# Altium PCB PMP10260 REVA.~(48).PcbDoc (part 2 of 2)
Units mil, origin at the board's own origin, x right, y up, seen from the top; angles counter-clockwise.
Board outline 5118.11 x 4724.41 mil, 4 copper layers (Top Layer, MidLayer1, MidLayer2, Bottom Layer), stack 63.8 mil thick; 175 components, 80 nets, 424 pads, 447 vias.
Unrouted connection lines stored in the file: 1.
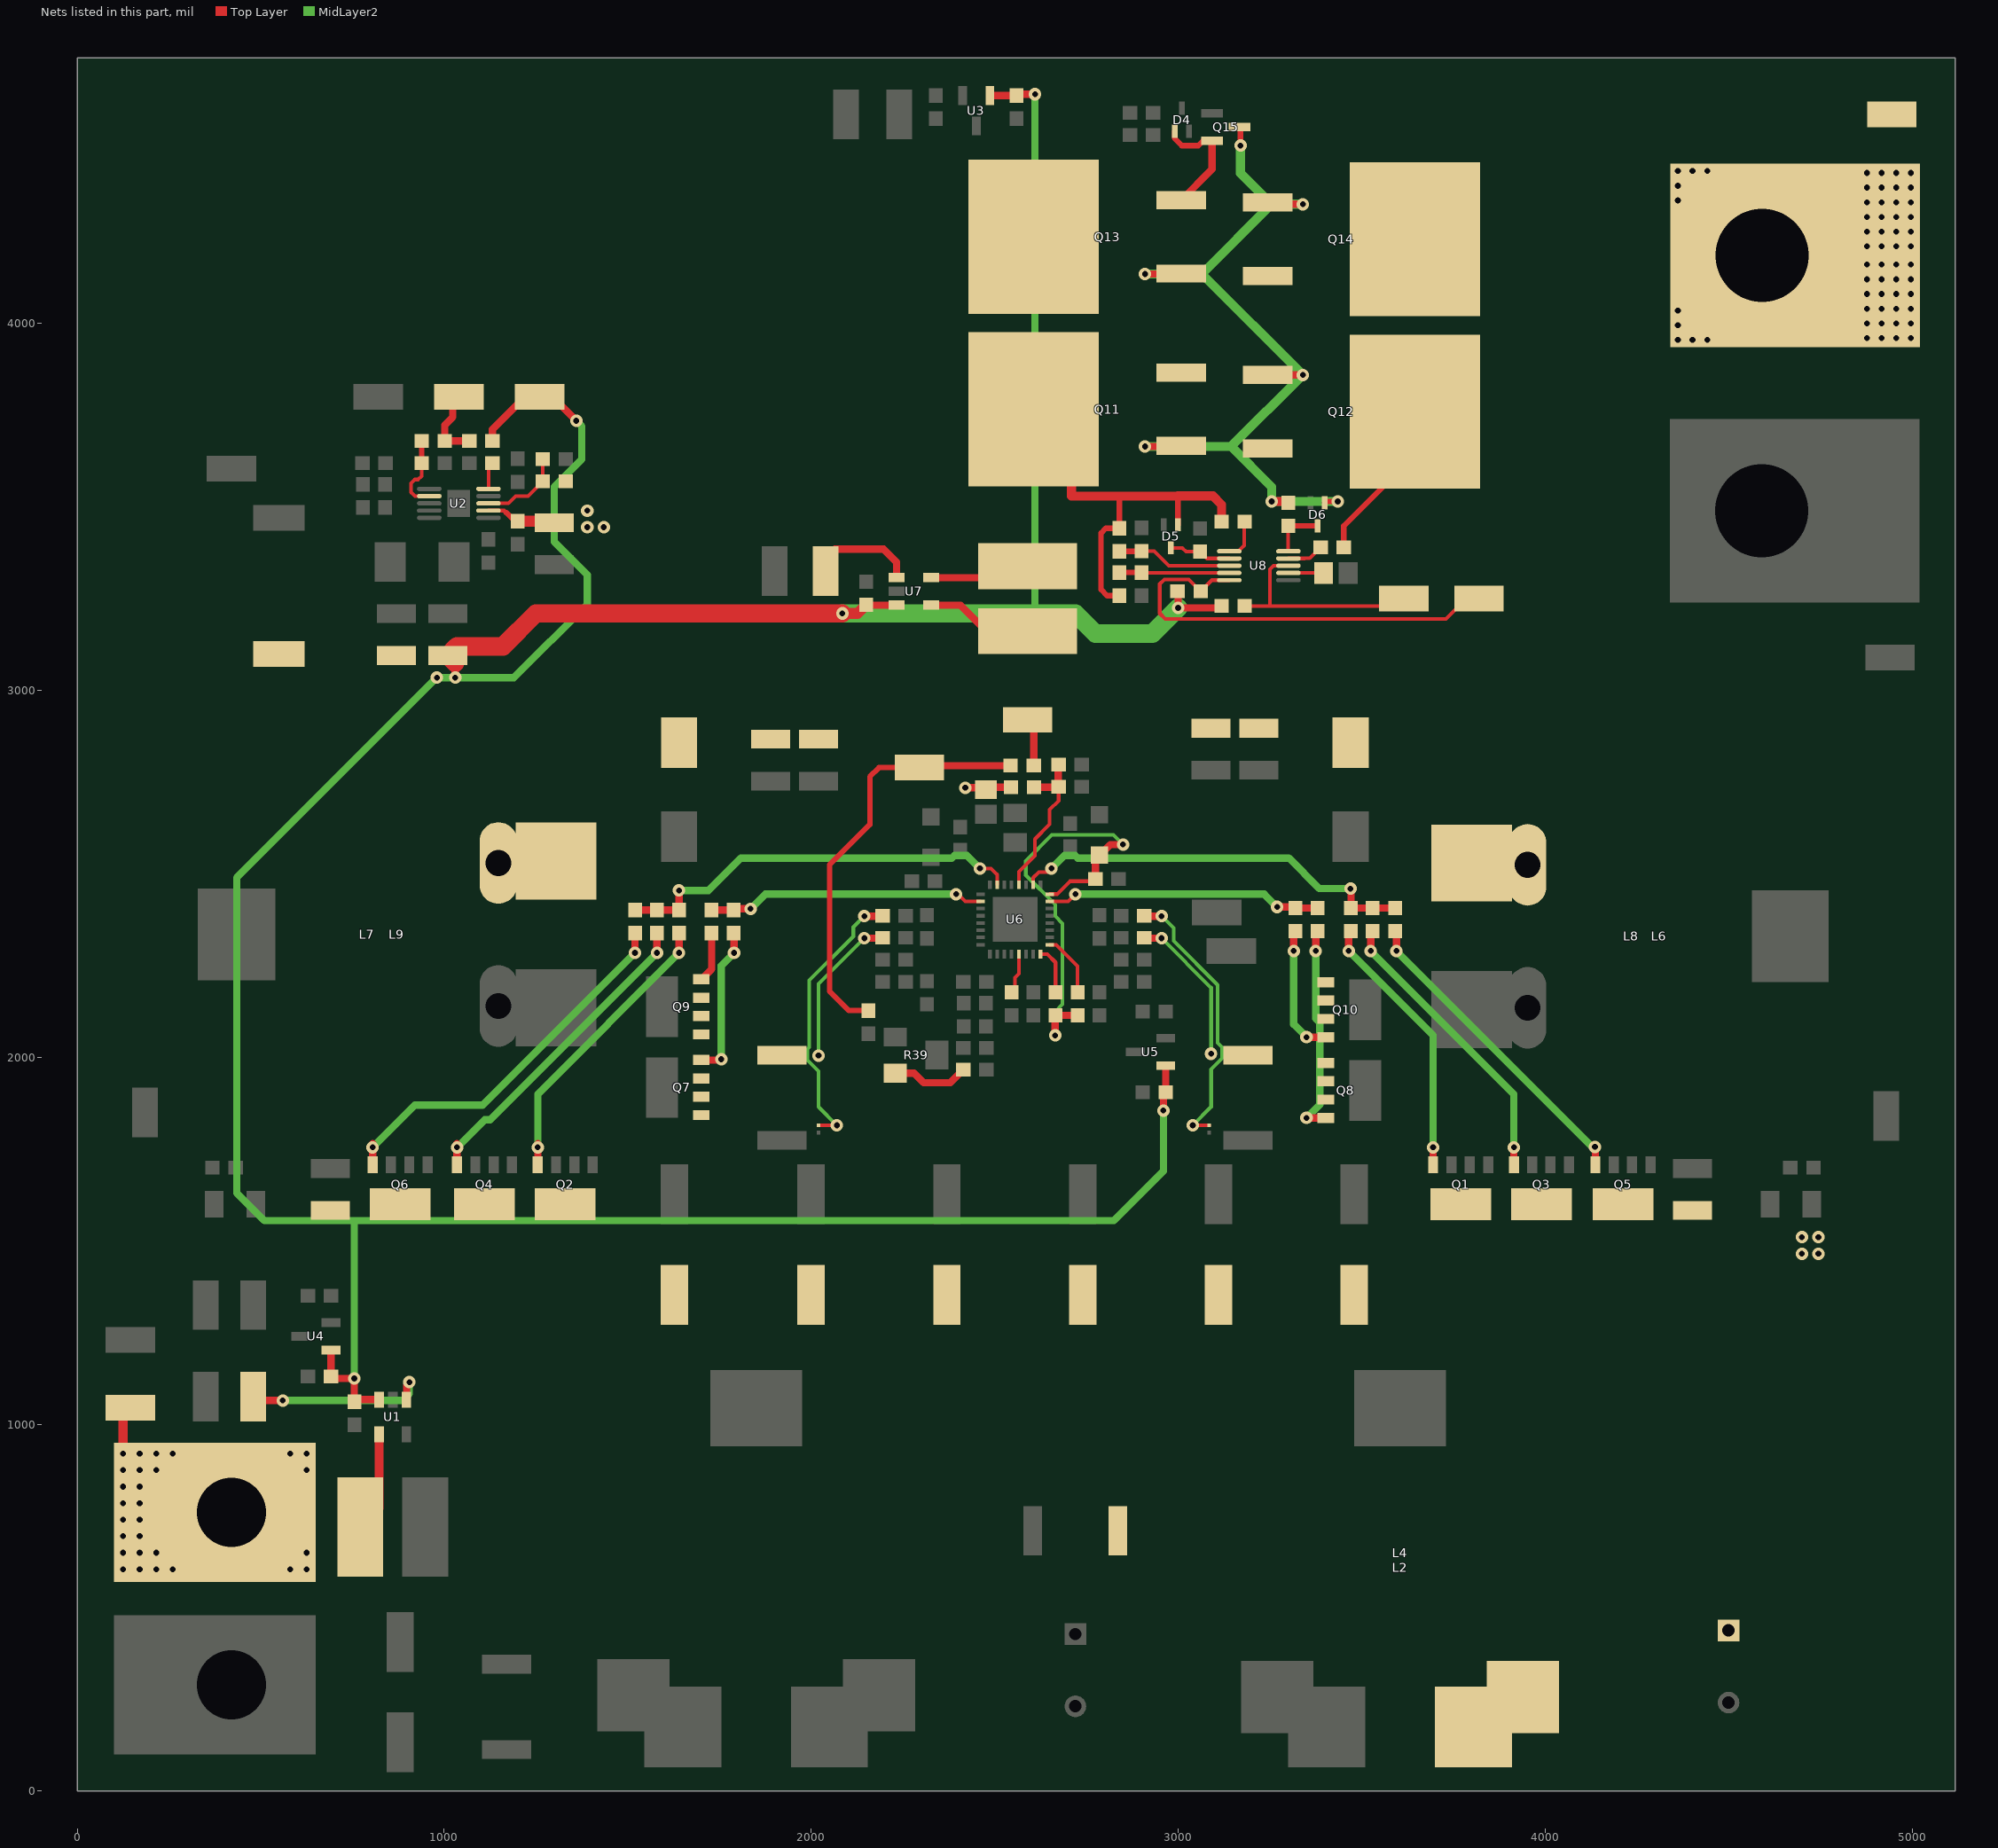
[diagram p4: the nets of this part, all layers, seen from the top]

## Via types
v1: diameter 34, hole 16, Top Layer to Bottom Layer, 260 vias
v2: diameter 32, hole 16, Top Layer to Bottom Layer, 172 vias
v3: diameter 19.68, hole 7.87, Top Layer to Bottom Layer, 10 vias
v4: diameter 200, hole 150, Top Layer to Bottom Layer, 5 vias

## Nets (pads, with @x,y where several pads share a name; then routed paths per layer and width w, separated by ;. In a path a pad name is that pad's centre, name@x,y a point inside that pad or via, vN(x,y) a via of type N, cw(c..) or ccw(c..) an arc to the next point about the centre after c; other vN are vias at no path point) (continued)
NetC52_1: C52.1 D5.3 U8.2 | length 171.2
  Top Layer w10: D5.3@2980,3388.5 3011.5,3388.5 3021.5,3378.5 C52.1@3060,3378.5 3078.82,3359.69 U8.2@3139.29,3359.69
NetC53_1: C53.1 U8.7 | length 96
  Top Layer w10: U8.7@3300.71,3320.31 3396.22,3320.31 C53.1@3396.54,3320
NetD4_1: D4.1 Q11.3 Q12.3 Q13.3 Q14.3 Q15.2 | length 332
  Top Layer w15: D4.1@2990.51,4523.9 2990.51,4504.49 3010,4485 3055,4485 3067.99,4497.99 Q15.2@3092.8,4497.99
  Top Layer w20: Q13.3@3008.15,4336.18 3092.8,4420.83 Q15.2@3092.8,4497.99
NetD5_1: D5.1 Q11.4 Q13.4 R43.2 R45.2 R46.2 R47.2 U7.5 | length 1509.8
  Top Layer w15: Q11.4@2606.57,3766.18 2606.57,3708.43 Q11.4@2709.69,3605.31 ; R46.2@2840,3258.5 2806.5,3258.5 2790,3275 2790,3428.94 2803.03,3441.97 R47.2@2840,3441.97 2840,3529.69 ; D5.1@2999.69,3451.5 2999.69,3529.69
  Top Layer w20: U7.5@2327.24,3307.4 2558.82,3307.4 R43.2@2590,3338.58
  Top Layer w25: Q11.4@2709.69,3663.07 2709.69,3605.31 2709.69,3529.69 2840,3529.69 2999.69,3529.69 ; 2999.69,3530 3095,3530 3118.5,3506.5 R45.2@3118.5,3460
NetD6_1: D6.1 Q11.1 Q12.1 Q13.1 Q14.1 Q15.3 R48.1 | length 2505.2
  Top Layer w15: Q15.3@3167.6,4535.39 3170,4532.99 v1(3170,4485) ; D6.1@3399.68,3511.5 3403.19,3515 v1(3435,3515)
  Top Layer w20: v1(2910,3665) 3006.97,3665 Q11.1@3008.15,3666.18 ; v1(2910,4135) 3006.97,4135 Q13.1@3008.15,4136.18 ; Q12.1@3243.94,3860 v1(3340,3860) ; Q14.1@3243.94,4330 3248.94,4325 v1(3340,4325)
  Top Layer w25: v1(3255,3515) 3296.5,3515 R48.1@3300,3511.5
  MidLayer2 w25: v1(2910,3665) 3145,3665 ; v1(2910,4135) 3065,4135 ; v1(3170,4485) 3170,4410 3255,4325 ; v1(3340,4325) 3255,4325 ; v1(3435,3515) v1(3255,3515) 3255,3555 3145,3665 ; 3065,4135 v1(3340,3860) 3145,3665 ; 3065,4135 3255,4325
NetD6_3: D6.3 R48.2 U8.10 | length 149.4
  Top Layer w10: R48.2@3300,3448.5 3300,3380.08 U8.10@3300.71,3379.37
  Top Layer w15: R48.2@3300,3448.5 D6.3@3380,3448.5
NetNT1_1: NT1.1 R34.2 | length 764.4
  Top Layer w10: v1(3040,1815) NT1.1@3085,1815
  Top Layer w20: R34.2@2907.56,2386.06 2908.62,2385 v1(2955,2385)
  MidLayer2 w10: v1(2955,2385) 2987.73,2352.27 2987.73,2317.73 3108,2197.46 3108,2040 3120,2028 3120,1997.57 3090,1967.57 3090,1865 v1(3040,1815)
NetNT2_2: NT2.2 R32.2 | length 765.8
  Top Layer w10: NT2.2@2020,1815 v1(2070,1815)
  Top Layer w20: v1(2145,2385) R32.2@2193.5,2385
  MidLayer2 w10: v1(2070,1815) 2020,1865 2020,1962.57 1990,1992.57 1990,2022.43 1995,2027.43 1995,2210 2115,2330 2115,2355 v1(2145,2385)
NetQ1_4: Q1.4 R16.2 | length 734.7
  Top Layer w20: v1(3465,2290) 3465,2337.76 R16.2@3471.3,2344.06 ; Q1.4@3695,1707.28 v1(3695,1755)
  MidLayer2 w20: v1(3465,2290) 3695,2060 v1(3695,1755)
NetQ2_4: Q2.4 R17.1 | length 800.8
  Top Layer w20: Q2.4@1254.84,1707.28 1255,1707.44 v1(1255,1755) v1@1255,1765 ; v1(1640,2285) R17.1@1640,2338.5
  MidLayer2 w20: v1(1255,1755) 1255,1900 v1(1640,2285)
NetQ3_4: Q3.4 R14.2 | length 800.4
  Top Layer w20: v1(3525,2290) 3525,2339.06 R14.2@3530,2344.06 ; Q3.4@3915,1707.28 v1(3915,1755)
  MidLayer2 w20: v1(3525,2290) 3915,1900 v1(3915,1755)
NetQ4_4: Q4.4 R15.1 | length 875.8
  Top Layer w20: Q4.4@1034.84,1707.28 1035,1707.44 v1(1035,1755) v1@1035,1765 ; v1(1580,2285) R15.1@1580,2338.5
  MidLayer2 w20: v1(1035,1755) 1110,1830 1125,1830 v1(1580,2285)
NetQ5_4: Q5.4 R18.2 | length 865.1
  Top Layer w20: R18.2@3591.3,2344.06 3595,2340.35 v1(3595,2290) ; Q5.4@4137.28,1707.44 v1@4137.28,1754.72
  MidLayer2 w20: v1(3595,2290) 4129,1756 v1(4136,1756)
NetQ6_4: Q6.4 R19.1 | length 1045.8
  Top Layer w20: Q6.4@804.84,1707.28 805,1707.44 v1(805,1755) v1@805,1765 ; v1(1520,2285) R19.1@1520,2338.5
  MidLayer2 w20: v1(805,1755) 920,1870 1105,1870 v1(1520,2285)
NetQ7_1: Q7.1 Q7.2 Q7.3 Q9.1 Q9.2 Q9.3 R28.2 R30.2 | length 421.8
  Top Layer w20: v1(2145,2325) 2193.5,2325 R28.2@2194.57,2326.06
  MidLayer2 w10: v1(2020,2005) 2020,2200 v1(2145,2325)
NetQ7_4: Q7.4 R20.1 | length 411.9
  Top Layer w20: Q7.4@1700.75,1992.72 1752.72,1992.72 v1(1755,1995) ; v1(1790,2285) R20.1@1790,2337.2
  MidLayer2 w20: v1(1755,1995) 1755,2250 v1(1790,2285)
NetQ8_1: Q8.1 Q8.2 Q8.3 Q10.1 Q10.2 Q10.3 R27.2 R29.2 | length 417.3
  Top Layer w20: R27.2@2908.62,2325 v1(2955,2325)
  MidLayer2 w10: v1(2955,2325) 3090,2190 v1(3090,2010)
NetQ8_4: Q8.4 R21.2 | length 583.7
  Top Layer w20: v1(3350,1835) Q8.4@3402.72,1835 ; v1(3375,2290) 3375,2339.06 R21.2@3380,2344.06
  MidLayer2 w20: v1(3350,1835) 3386.42,1871.42 3386.42,2094.52 3375,2105.94 v1(3375,2290)
NetQ9_4: Q9.4 R24.1 | length 137.4
  Top Layer w20: Q9.4@1700.75,2212.72 1728.7,2240.67 R24.1@1728.7,2338.5
NetQ10_4: Q10.4 R25.2 | length 358.3
  Top Layer w20: v1(3315,2290) 3315,2339.06 R25.2@3320,2344.06 ; v1(3350,2055) Q10.4@3402.72,2055
  MidLayer2 w20: v1(3315,2290) 3315,2090 v1(3350,2055)
NetQ12_4: Q12.4 Q14.4 R49.1 T3.1 TP19.1 | length 450.4
  Top Layer w15: R49.1@3451.5,3390 3451.5,3448.5 3645.51,3642.52 Q12.4@3645.51,3760
  other v2: 4361.89,3955.55 4401.89,3955.55 4441.89,3955.55 4876.89,3960.55 4916.89,3960.55 4956.89,3960.55 4996.89,3960.55 4361.89,3995.55 4876.89,4000.55 4916.89,4000.55 4956.89,4000.55 4996.89,4000.55 4361.89,4035.55 4876.89,4040.55 4916.89,4040.55 4956.89,4040.55 4996.89,4040.55 4876.89,4080.55 4916.89,4080.55 4956.89,4080.55 4996.89,4080.55 4876.89,4120.55 4916.89,4120.55 4956.89,4120.55 4996.89,4120.55 4876.89,4160.55 4916.89,4160.55 4956.89,4160.55 4996.89,4160.55 4876.89,4210.55 4916.89,4210.55 4956.89,4210.55 4996.89,4210.55 4876.89,4250.55 4916.89,4250.55 4956.89,4250.55 4996.89,4250.55 4876.89,4290.55 4916.89,4290.55 4956.89,4290.55 4996.89,4290.55 4876.89,4330.55 4916.89,4330.55 4956.89,4330.55 4996.89,4330.55 4361.89,4335.55 4876.89,4370.55 4916.89,4370.55 4956.89,4370.55 4996.89,4370.55 4361.89,4375.55 4876.89,4410.55 4916.89,4410.55 4956.89,4410.55 4996.89,4410.55 4361.89,4415.55 4401.89,4415.55 4441.89,4415.55
NetR3_1: R3.1 T1.1 TP1.1 U1.4 | length 407.2
  Top Layer w25: v2(125,920) 125,1025 TP1.1@145,1045 ; R3.1@771.42,720 822.6,771.18 U1.4@822.6,972.75
  other v2: 125,605 170,605 215,605 260,605 580,605 625,605 125,650 170,650 215,650 625,650 125,695 170,695 125,740 170,740 125,785 170,785 125,830 170,830 125,875 170,875 215,875 625,875 170,920 215,920 260,920 580,920 625,920
NetR4_1: R4.1 R6.2 TP7.1 | length 203.4
  Top Layer w20: TP7.1@1040,3800 1023.03,3783.03 1023.03,3745 1001.52,3723.48 R6.2@1001.52,3679.65 1001.86,3680 R4.1@1068.5,3680
NetR5_1: R5.1 R9.2 U2.3 | length 232.6
  Top Layer w10: U2.3@1120.73,3509.97 1174.97,3509.97 1195,3530 1228.56,3530 R5.1@1268.52,3569.97 R9.2@1268.52,3629.97
NetR6_1: R6.1 R7.2 U2.7 | length 210.4
  Top Layer w10: R7.2@938.52,3619.97 938.52,3584.36 929.17,3575 920,3575 910,3565 910,3540 920.35,3529.65 U2.7@959.31,3529.65
  Top Layer w15: R7.2@938.52,3619.97 R6.1@938.52,3679.65
NetR10_2: R10.2 U2.5 | length 75.1
  Top Layer w10: U2.5@1120.73,3549.34 1120.73,3609.18 R10.2@1131.52,3619.97
NetR14_1: R14.1 R16.1 R18.1 U6.26 | length 1119.7
  Top Layer w10: U6.26@2605.28,2470.55 2605.28,2489.82 2620.46,2505 2645,2505 v1(2655,2515)
  Top Layer w20: v1(3470,2460) 3471.3,2458.7 R16.1@3471.3,2407.05 R14.1@3530,2407.05 R18.1@3591.3,2407.05
  MidLayer2 w20: v1(2655,2515) 2690,2550 2719.5,2550 2726.5,2543 3301.6,2543 3384.6,2460 v1(3470,2460)
NetR15_2: R15.2 R17.2 R19.2 U6.31 | length 1128.8
  Top Layer w10: v1(2460,2515) 2490,2515 2506.85,2498.15 U6.31@2506.85,2470.55
  Top Layer w20: R19.2@1520,2401.5 R15.2@1580,2401.5 R17.2@1640,2401.5 v1(1640,2455)
  MidLayer2 w20: v1(1640,2455) 1720.4,2455 1808.4,2543 2383.5,2543 2390.5,2550 2425,2550 v1(2460,2515)
NetR20_2: R20.2 R24.2 U6.2 | length 754.1
  Top Layer w10: v1(2395,2445) 2400.55,2445 2420.28,2425.28 U6.2@2461.57,2425.28
  Top Layer w20: R24.2@1728.7,2401.5 R20.2@1788.7,2401.5 ; R20.2@1792.2,2405 v1(1835,2405)
  MidLayer2 w20: v1(1835,2405) 1875,2445 v1(2395,2445)
NetR21_1: R21.1 R25.1 U6.23 | length 753.3
  Top Layer w10: U6.23@2650.55,2425.28 2700.28,2425.28 v1(2720,2445)
  Top Layer w20: v1(3270,2410) 3317.05,2410 R25.1@3320,2407.05 R21.1@3380,2407.05
  MidLayer2 w20: v1(2720,2445) 3235,2445 v1(3270,2410)
NetR22_1: R22.1 U6.16 | length 131.9
  Top Layer w10: U6.16@2624.96,2281.57 2643.43,2281.57 2666.06,2258.94 R22.1@2666.06,2177.56
NetR35_1: R35.1 R37.2 TP18.1 | length 1154.3
  Top Layer w15: R37.2@2156.06,2127.56 2102.44,2127.56 2050,2180 2050,2525 2160,2635 2160,2765 2185,2790 TP18.1@2295,2790
  Top Layer w20: TP18.1@2295,2790 2300,2795 R35.1@2543.5,2795
NetR36_2: R36.2 U6.17 | length 171
  Top Layer w10: U6.17@2650.55,2307.17 2667.83,2307.17 2726.06,2248.94 R36.2@2726.06,2177.56
NetR39_3: R39.3 R42.2 | length 210.8
  Top Layer w20: R39.3@2228.98,1956.85 2280.76,1956.85 2306.56,1931.04 2379.55,1931.04 R42.2@2414.57,1966.06
NetR41_2: R41.2 U6.13 | length 112.2
  Top Layer w10: R41.2@2546.06,2177.56 2555,2186.5 2555,2217.57 2565.91,2228.48 U6.13@2565.91,2281.57
NetR45_1: R45.1 U8.1 | length 112.8
  Top Layer w10: U8.1@3139.29,3379.37 3164.37,3379.37 3180,3395 3180,3458.5 R45.1@3181.5,3460
NetR46_1: R46.1 R50.2 U8.4 | length 299.8
  Top Layer w10: R50.2@2901.18,3320.31 U8.4@3139.29,3320.31
  Top Layer w15: R46.1@2840,3321.5 R50.2@2900,3321.5 R50.2@2901.18,3320.31
NetR47_1: R47.1 R51.2 U8.3 | length 316.3
  Top Layer w10: R51.2@2900,3380 2935,3380 2975,3340 U8.3@3139.29,3340
  Top Layer w15: R47.1@2840,3378.98 2898.98,3378.98 R51.2@2900,3380
NetR49_2: R49.2 U8.9 | length 100.4
  Top Layer w10: U8.9@3300.71,3359.69 3344.69,3359.69 3345,3360 3358.5,3360 R49.2@3388.5,3390
NetR52_2: R52.2 TP22.1 U8.8 | length 596.6
  Top Layer w10: R52.2@3181.5,3230 3250,3230 ; U8.8@3300.71,3340 3260,3340 3250,3330 3250,3230 ; TP22.1@3615,3250 3595,3230 3250,3230
NetR53_2: R53.2 TP24.1 U8.5 | length 1199.5
  Top Layer w10: U8.5@3139.29,3300.63 3092.13,3300.63 R53.2@3061.5,3270 3029.18,3302.31 2962.32,3302.31 2950,3290 2950,3210 2965,3195 3730,3195 3785,3250 TP24.1@3820,3250
NetTP3_1: TP3.1 U1.1 | length 519.4
  Top Layer w20: TP3.1@480,1075 490,1065 v1(560,1065) ; U1.1@897.41,1067.24 897.41,1107.41 v1(905,1115)
  MidLayer2 w20: v1(560,1065) 886.85,1065 905,1083.15 v1(905,1115)
NetTP21_1: TP21.1 U7.1 | length 295.2
  Top Layer w20: TP21.1@2040,3325 2040,3360 2065,3385 2197.76,3385 2232.76,3350 U7.1@2232.76,3307.4
UVLO: C27.1 R11.1 R13.2 U6.28 | length 439.4
  Top Layer w10: U6.28@2565.91,2470.55 2565.91,2505.91 2610,2550 2610,2595 2650,2635 2650,2675 2674.57,2699.57 C27.1@2674.57,2737.36
  Top Layer w20: R11.1@2607.56,2736.06 2673.27,2736.06 2673.27,2796.06 R13.2@2674.57,2797.36
VCC2: C30.1 D3.2 R22.2 R36.1 U6.24 | length 1231.6
  Top Layer w10: U6.24@2650.55,2444.96 2669.96,2444.96 2705,2480 2768.5,2480 C30.1@2774.57,2486.06 ; D3.2@2774.57,2539.45 D3.2@2786.06,2550.95
  Top Layer w20: v1(2665,2060) 2665,2113.5 R22.2@2666.06,2114.57 R36.1@2726.06,2114.57 ; C30.1@2774.57,2486.06 D3.2@2774.57,2539.45 ; D3.2@2786.06,2550.95 2815.12,2580 v1(2850,2580)
  MidLayer2 w10: v1(2665,2060) 2665,2124.41 2685,2144.41 2685,2365 2665,2385 2665,2416.18 2585,2496.18 2585,2535 2656.06,2606.06 2823.94,2606.06 v1(2850,2580)
VCC_5V: C4.1 C7.1 C8.1 C13.1 C15.1 C17.1 C51.1 L5.2 R4.2 R52.1 R53.1 TP6.1 U1.3 U3.1 U4.1 U5.1 U7.3 | length 10646.8
  Top Layer w20: U4.1@691.34,1202.6 691.34,1130.16 C15.1@691.5,1130 696.5,1125 v1(755,1125) C4.1@755,1061.5 760.75,1067.24 U1.3@822.6,1067.24 ; v1(1030,3035) C8.1@1030,3075.03 ; R4.2@1131.5,3680 1131.5,3711.5 1220,3800 TP6.1@1260,3800 1295,3800 v1(1360,3735) ; C51.1@2150,3232.6 U7.3@2232.76,3232.6 ; U3.1@2487.4,4621.34 2559.84,4621.34 C13.1@2560,4621.5 2563.5,4625 v1(2610,4625) ; v1(2960,1855) 2960,1898.82 C17.1@2966.18,1905 2966.18,1977.44 U5.1@2966.02,1977.6 ; R53.1@2998.5,3270 3000,3268.5 v1(3000,3225) 3113.5,3225 R52.1@3118.5,3230
  Top Layer w30: v1(2085,3210) 2126.5,3210 C51.1@2150,3233.5
  Top Layer w50: C8.1@1030,3075.03 C8.1@1009.7,3095.32 1034.38,3120 1160,3120 1250,3210 v1(2085,3210)
  MidLayer2 w20: v1(755,1125) 755,1555 ; v1(1360,3735) 1375,3720 1375,3630 1300.02,3555.02 1300.02,3404.98 1390,3315 1390,3235 1190,3035 v1(1030,3035) v1(980,3035) 435,2490 435,1630 510,1555 755,1555 ; 2610,3210 v1(2610,4625) ; v1(2960,1855) 2960,1690 2825,1555 755,1555
  MidLayer2 w50: v1(2085,3210) 2610,3210 2720,3210 2775,3155 2930,3155 v1(3000,3225)
VIN: C3.1 C5.1 C6.1 C19.1 C20.1 C21.1 C22.1 C23.1 C24.1 C25.1 C26.1 L2.2 L4.2 Q1.5 Q2.5 Q3.5 Q4.5 Q5.5 Q6.5 R2.2 R5.2 R11.2 R12.1 U2.2 | length 322.6
  Top Layer w10: U2.2@1120.73,3490.28 1163.75,3490.28 1169.04,3485
  Top Layer w15: 1169.04,3485 1192.57,3461.46 C6.1@1200.02,3461.46
  Top Layer w20: v1(2420,2735) 2470.59,2735 R12.1@2476.06,2729.53 2482.6,2736.06 R11.2@2544.57,2736.06
  Top Layer w30: C6.1@1200.02,3461.46 1295.61,3461.46 C5.1@1300.02,3457.05
  other v1: 4700,1465 4745,1465 4700,1510 4745,1510 1390,3445 1435,3445 1390,3490
VOUT: C34.1 C35.1 C36.1 C37.1 C39.1 C40.1 L6.2 L7.1 L8.1 L9.2 R35.2 R43.1 TP17.1 U7.4 | length 424.1
  Top Layer w20: U7.4@2327.24,3232.6 2407.4,3232.6 2478.58,3161.42 R43.1@2590,3161.42 ; TP17.1@2590,2920 2606.5,2903.5 R35.2@2606.5,2795
pads on no net: D4.2 D5.2 D6.2 L1.3 L2.3 L3.3 L4.3 L6.3 L7.3 L8.3 L9.3 U2.6 U6.8 U6.11
copper on no net:
  other v4: 165,1575 4940,1580 2680,1900 1240,4510 4140,4510

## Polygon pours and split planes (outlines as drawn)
GND on Top Layer "Top Layer-No Net 20" (solid, pour order 24): -2.5,0 0,2.5 0,4726.91 5115.61,4726.91 5118.11,4724.41 5118.11,-2.5
VIN on Top Layer "Top Layer-No Net 21" (solid, pour order 26): 900,1175 745,1175 730,1190 730,1385 685,1430 355,1430 330,1455 330,1515 355,1540 530,1540 580,1590 580,1610 897.56,1609.84
NetR3_1 on Top Layer "Top Layer-No Net" (solid, pour order 2): 100,950 830,950 830,570 450,570 100,570
NetC2_1 on Top Layer "Top Layer-No Net 2" (solid, pour order 6): 1093.23,190 1093.23,78.43 1246.77,78.43 1246.77,190
NetC31_2 on Top Layer "Top Layer-No Net 5" (solid, pour order 12): 1635,2220 1635,1835 1595,1795 1485,1685 840,1685 840,1765 840,1770 825,1785 820,1790 620,1790 605,1790 570,1755 515,1700 505,1700 481.02,1700 461.02,1680 459.72,1681.3 410,1681.3 410,1718.7 410,1735 395,1750 150,1750 115,1785 115,2180 575,2180 600,2205 720,2325 1405,2325 1495,2235 1505,2235 1635,2235
NetC1_1 on Top Layer "Top Layer-No Net 1" (solid, pour order 4): 890,851.89 890,340 900,330 950,330 980,330 1070,240 1270,240 1290,220 1290,0 1830,0 1830,550 1830,830 1810,850 1808.11,851.89 960,851.89 900,851.89
NetC2_1 on Top Layer "Top Layer-No Net 3" (solid, pour order 8): 1930,30 1930,810 1950,830 1960,840 1960,850 2555.94,850 2630,775.94 2630,644.06 2630,610 2660,580 3310,580 3340,580 3570,350 3570,0 1932.5,0 1930,-2.5
VIN on Top Layer "Top Layer-No Net 4" (solid, pour order 10): 3650,-2.5 5118.11,-2.5 5118.11,1500 5120.61,1502.5 5120.61,1540 4570,1540 4510,1600 4470,1640 3590,1640 3580,1640 3560,1620 3560,1550 3560,1530 3540,1510 3340,1510 1640,1510 1610,1510 1570,1510 1550,1530 1550,1610 1520,1640 1340,1640 610,1640 580,1610 580,1530 580,1490 580,1480 600,1460 740,1460 840,1360 940,1360 960,1360 1140,1180 1148.19,1171.81 2010,1171.81 2018.19,1171.81 2050,1140 2050,1030 2110,970 2120,960 2650,960 2670,960 2750,880 2780,850 2780,700 2780,653.23 2793.23,640 2910,640 3370,640 3550,460 3630,380 3630,350 3630,0
VIN on Top Layer "Top Layer-No Net 6" (solid, pour order 14): 840,1360 840,1235 885,1190 900,1175 930,1175 960,1145 960,1030 1030,960 1590,960 1595,960 1655,1020 1655,1140 1658.19,1140 1685,1166.81 2110,1166.81 2110,1265 2080,1295 1180,1295 1140,1295 1045,1390 1025,1410 840,1410
NetC32_2 on Top Layer "Top Layer-No Net 8" (solid, pour order 20): 4305,1685 3725,1685 3725,1775 3690,1810 3465,1810 3465,1960 3465,2235 3615,2235 3660,2280 3705,2325 3775,2325 4350,2325 4475,2200 4510,2165 4695,2165 4960,2165 5000,2165 5000,1780 4960,1740 4720,1740 4715,1740 4711.3,1740 4690,1718.7 4681.3,1710 4680,1710 4655,1710 4645,1720 4565,1720 4495,1790 4350,1790 4330,1790 4305,1765
NetC32_2 on Top Layer "Top Layer-No Net 9" (solid, pour order 22): 4910,1740 5118.11,1740 5118.11,2745 4978.11,2885 4945,2885 4475,2885 4340,2750 4335,2745 4335,2455 4190,2310 4525,1975 4910,1975
NetC31_2 on Top Layer "Top Layer-No Net 10" (solid, pour order 24): 260,1750 0,1750 0,2775 110,2885 115,2885 615,2885 720,2780 720,2455 860,2315 885,2290 885,2030 295,2030 260,1995
NetQ8_1 on Top Layer "Top Layer-No Net 11" (solid, pour order 26): 3425,2085 3425,2225 3190,2225 3155,2225 3150,2225 3115,2190 3115,2145 3115,2140 3090,2115 3060,2085 3060,2020 3060,1892.01 3127.01,1825 3235,1825 3285,1825 3325,1865 3425,1865
VOUT on Top Layer "Top Layer-No Net 12" (solid, pour order 28): 770,2470 865,2375 1415,2375 1515,2475 1515,2650 1515,2670 1570,2725 1720,2725 1735,2725 1815,2805 2100,2805 2140,2805 2195,2860 2795,2860 2850,2805 3305,2805 3310,2805 3390,2725 3555,2725 3590,2690 3590,2475 3660,2405 3690,2375 3785,2375 4185,2375 4295,2485 4295,2745 4160,2880 3890,3150 2850,3150 2791.89,3150 2721.89,3220 2716.89,3225 2455,3225 2380,3150 1505,3150 1340,3150 1145,2955 1143.82,2955 1075,2886.18 1073.82,2885 770,2885
NetQ7_1 on Top Layer "Top Layer-No Net 13" (solid, pour order 30): 1675,2180 1675,1825 1965,1825 2040,1900 2040,2110 2000,2150 2000,2205 1980,2225 1755,2225 1755,2190 1745,2180
NetD5_1 on Top Layer "Top Layer-No Net 7" (solid, pour order 32): 2455,3275 2735,3275 2760,3300 2760,3480 2760,3485 2800,3525 2800,3549.65 2800,4719.41 2805,4724.41 0,4724.41 0,3905 1385,3905 1445,3845 1450,3840 1450,3595 1450,3590 1520,3520 2150,3520 2220,3520 2345,3395 2400,3340 2400,3307.4 2432.4,3275 2470,3275
NetQ12_4 on Top Layer "Top Layer-No Net 14" (solid, pour order 34): 3465,3543.46 3465,4724.41 5120.61,4724.41 5118.11,4721.91 5118.11,3775 4320,3775 4305,3760 4305,3275 4305,3260 4280,3235 4020,3235 3980,3235 3955,3260 3950,3265 3950,3305 3950,3310 3925,3335 3920,3340 3590,3340 3545,3385 3545,3410 3545,3460
NetD4_1 on Top Layer "Top Layer-No Net 16" (solid, pour order 38): 2835,3560 2835,3800 2835,4428.82 2840,4433.82 2841.18,4435 3180,4435 3205,4435 3230,4460 3230,4726.91 3232.5,4724.41 3425,4724.41 3425,3560
VIN on Top Layer "Top Layer-No Net 15" (solid, pour order 40): 1163.75,3490.28 1164.46,3490.99 1185,3490.99 1185.99,3490.99 1205,3510 1245,3510 1265,3530 1310,3530 1310,3588.67 1311.33,3590 1350,3590 1355,3590 1355,3430 1230,3430 1210,3450 1198.54,3461.46 1192.57,3461.46
NetC9_1 on Top Layer "Top Layer-No Net 17" (solid, pour order 42): 985,3475 755,3475 700,3475 695,3475 660,3510 519,3651 342,3651 342,3313 360,3295 965,3295 965,3415 970,3420 980,3420 983.06,3420 991.53,3428.47 990,3430 990,3475
VCC_5V on Top Layer "Top Layer-No Net 18" (solid, pour order 44): 360,3235 340,3215 340,3055 340,3045 365,3020 370,3015 590,3015 1050,3015 1065,3030 1062.85,3032.15 1062.85,3145 795,3145 775,3165 765,3175 765,3215 745,3235
VIN on Top Layer "Top Layer-No Net 19" (solid, pour order 46): 1335,3430 1455,3430 1455,3460 1445,3470 1385,3530 1340,3530
GND on MidLayer2 "MidLayer2-No Net 1" (solid, pour order 32): 5,0 0,5 0,4726.91 5118.11,4726.91 5120.61,4724.41 5118.11,4721.91 5118.11,0
VIN on MidLayer2 "MidLayer2-No Net" (solid, pour order 22): 4665,1515 4665,1435 4780,1435 4780,1560 4780,2270 4010,3040 4005,3035 2155,3035 1980,3035 1495,3520 1380,3520 1375,3520 1370,3515 1370,3430 1380,3420 1455,3420 1475,3420 1605,3290 1940,2955 2010,2955 2385,2955 2395,2945 2395,2745 2395,2725 2410,2710 2430,2710 2432.52,2710 2447.52,2725 2445,2727.52 2445,2945 2455,2955 2690,2955 3820,2955 3965,2955 3975,2955 4170,2760 4520,2410 4615,2315 4665.57,2264.43 4665.57,1700
GND on MidLayer1 "MidLayer1-No Net" (solid, pour order 28): 15,4705 34.41,4724.41 5118.11,4724.41 5118.11,2.5 5120.61,0 0,0
GND on Bottom Layer "Bottom Layer-No Net" (solid, pour order 30): 0,4726.91 5115.61,4726.91 5118.11,4724.41 5118.11,0 -2.5,0

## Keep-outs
Keep-Out Layer:
  lines w5: -2.5,0 ccw(c0,0) 0,-2.5 ; -2.5,0 ccw(c0,0) 0,-2.5 ; -2.5,0 -2.5,4724.41 ; -2.5,4724.41 cw(c0,4724.41) 0,4726.91 ; -2.5,4724.41 cw(c0,4724.41) 0,4726.91 ; 0,-2.5 5118.11,-2.5 ; 0,4726.91 5118.11,4726.91 ; 5118.11,-2.5 ccw(c5118.11,0) 5120.61,0 ; 5118.11,-2.5 ccw(c5118.11,0) 5120.61,0 ; 5118.11,4726.91 cw(c5118.11,4724.41) 5120.61,4724.41 ; 5118.11,4726.91 cw(c5118.11,4724.41) 5120.61,4724.41 ; 5120.61,0 5120.61,4724.41
  lines w7.01: 0,0 5118.11,0 5118.11,4724.41 0,4724.41 0,0
  text ".Layer_Name" at 577,-858.49 h60

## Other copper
Top Layer:
  pour cut-out: 795,560 795,300 820,275 955,275 1040,190 1040,15 1280,15 1280,65 1265,80 1255,70 1090,70 1088.55,71.45 1088.55,219.61 1080.39,219.61 980,320 975,315 840,315 840,560
  pour cut-out: 2095,945 2670,945 2759.61,855.39 2759.61,654.45 2780.83,633.23 3347.93,633.23 3611.16,370 3620,370 3620,15 3585,15 3585,355 3350,590 2665,590 2635,620 2635,770.94 2630,775.94 2630,790 2625,790 2545,870 2090,870
  pour cut-out: 950,1010 950,1096.32 941.32,1105 930,1105 930,1095 916.93,1081.93 916.93,1040 880,1040 875,1035 875,1000 860.32,1000 860,1000.31 859.69,1000 840,1000 840,575 825,560 827.6,557.4 827.6,497.4 830,495 885,495 885,995 880,1000
  pour cut-out: 1845,840 1815,870 960,870 960,875 917.5,917.5 917.5,1020 940,1020 1015,945 1600,945 1665,1010 1665,1115 1690,1140 1705,1140 1705,925 2000,925 2000,1145 2020,1145 2035,1130 2035,1000 2060,1000 2110,950 2110,870 1955,870 1915,830 1915,20 1850,20 1845,25
  text ".Layer_Name" at 577,-858.49 h60
Bottom Layer:
  text ".Layer_Name" at 577,-858.49 h60

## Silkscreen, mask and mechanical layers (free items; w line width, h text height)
Top Overlay:
  text ".PRJ_Number" at 4300,830 h60
  text ".PCB_Rev" at 4890,830 h60
  text ".Layer_Name" at 577,-858.49 h60
Bottom Overlay:
  text ".Layer_Name" at 577,-858.49 h60
Top Paste:
  text ".Layer_Name" at 577,-858.49 h60
Bottom Paste:
  text ".Layer_Name" at 577,-858.49 h60
Top Solder:
  text ".Layer_Name" at 577,-858.49 h60
  text ".Layer_Name" at 577,-858.49 h60
Bottom Solder:
  text ".Layer_Name" at 577,-858.49 h60
Drill Guide:
  text ".Layer_Name" at 577,-858.49 h60
M1 Board Outline:
  the board outline again, w7.01
  text ".Layer_Name" at 577,-858.49 h60
M2 Board Dimensions:
  rectangle: -0.5,-285.5 124.5,-160.5
  rectangle: 124.5,-410.5 499.5,-285.5
  lines w7: -0.5,-285.5 999.5,-285.5 ; 124.5,-410.5 124.5,-160.5 ; 249.5,-410.5 249.5,-160.5 ; 499.5,-410.5 499.5,-160.5 ; 749.5,-410.5 749.5,-160.5 ; -0.5,-410.5 999.5,-410.5 999.5,-160.5 -0.5,-160.5 -0.5,-410.5
  lines w10: -0.5,-475.5 -0.5,-455.5 ; 59.5,-485.5 -0.5,-465.5 ; 59.5,-445.5 -0.5,-465.5 ; 223.58,-465.5 -0.5,-465.5 ; 775.42,-465.5 999.5,-465.5 ; 939.5,-485.5 999.5,-465.5 ; 939.5,-445.5 999.5,-465.5 ; 999.5,-475.5 999.5,-455.5
  text "1000 (mil)" at 233.58,-501.49 h60
  text ".Layer_Name" at 577,-858.49 h60
M3 3D STEP Top:
  text ".Layer_Name" at 577,-858.49 h60
M4 3D STEP Bottom:
  text ".Layer_Name" at 577,-858.49 h60
M5 Assembly Top:
  lines w10: -292,-930.17 6308,-930.17 ; -292,-726.83 6310,-726.83 ; -292,-523.5 -292,-1133.5 3713,-1133.5 6310,-1133.5 6310,-523.5 -291.5,-523.5 -291.5,-1133.5 1284,-1133.5 ; 2173,-1133.5 2173,-523.5 ; 3440,-726.83 3440,-523.5 ; 4280,-726.83 4280,-523.5 ; 4902,-1140 4902,-937.17
  text "COMPONENTS MARKED 'DNP' SHOULD NOT BE POPULATED." at 1153.5,-318.5 h60
  text "ASSEMBLY VARIANT:" at 1153,-434 h60
  text ".VariantName" at 2189,-434 h60
  text "PCB VIEWED FROM TOP SIDE" at -228.5,-655.67 h60
  text "BOARD #:" at 2248,-655.67 h60
  text ".PRJ_Number" at 2793.5,-655.67 h60
  text "REV:" at 3638,-655.67 h60
  text ".PCB_Rev" at 3929.5,-655.67 h60
  text "SVN REV:" at 4476,-655.67 h60
  text ".VersionControl_RevNumber" at 4982,-655.67 h60
  text "IGNORE ->" at -228.5,-858.49 h60
  text "PLOT NAME =" at -228.5,-1064.34 h60
  text ".plot_File_Name" at 577,-1064.34 h60
  text "GENERATED    :" at 2250,-1064.34 h60
  text ".Print_Date" at 3119.5,-1064.34 h60
  text ".Print_Time" at 3848.5,-1064.34 h60
  text "TEXAS INSTRUMENTS" at 5113,-1064.34 h60
M6 Assembly Bottom:
  lines w10: -292.5,-727.33 6309.5,-727.33 ; -290.5,-930.67 6309.5,-930.67 ; 1115.5,-1140.5 1115.5,-937.67 ; 1737.5,-727.33 1737.5,-524 ; 2577.5,-727.33 2577.5,-524 ; 3844.5,-1134 3844.5,-524 ; 4733.5,-1134 6309,-1134 6309,-524 -292.5,-524 -292.5,-1134 2304.5,-1134 6309.5,-1134 6309.5,-524
  text "COMPONENTS MARKED 'DNP' SHOULD NOT BE POPULATED." at 6102,-318 h60
  text ".VariantName" at 5058,-434 h60
  text "ASSEMBLY VARIANT:" at 6097,-434 h60
  text ".VersionControl_RevNumber" at 1035.5,-656.17 h60
  text "SVN REV:" at 1541.5,-656.17 h60
  text ".PCB_Rev" at 2088,-656.17 h60
  text "REV:" at 2379.5,-656.17 h60
  text ".PRJ_Number" at 3224,-656.17 h60
  text "BOARD #:" at 3769.5,-656.17 h60
  text "PCB VIEWED FROM BOTTOM SIDE" at 6246,-656.17 h60
  text "IGNORE ->" at 2547.85,-858.49 h60
  text "TEXAS INSTRUMENTS" at 904.5,-1064.84 h60
  text ".Print_Time" at 2169,-1064.84 h60
  text ".Print_Date" at 2898,-1064.84 h60
  text "GENERATED    :" at 3767.5,-1064.84 h60
  text ".plot_File_Name" at 5440.5,-1064.84 h60
  text "PLOT NAME =" at 6246,-1064.84 h60
M9 Title Sheet:
  drawing of 57 lines, arcs and shapes, not listed
  text "1" at 739.84,8036.5 h70
  text "2" at 3235.5,8036.5 h70
  text "3" at 5724.84,8036.5 h70
  text "4" at 8231.51,8036.5 h70
  text "5" at 10730.5,8036.5 h70
  text "6" at 13235.5,8036.5 h70
  text "A" at -416.5,6893.5 h70
  text "A" at 14383.5,6893.5 h70
  text "B" at -416.5,4513.5 h70
  text "B" at 14383.5,4513.5 h70
  text "C" at -416.5,2138.5 h70
  text "C" at 15285.5,1822.5 h70
  text "PROJECT TITLE:" at 11343.5,277.5 h45
  text ".PRJ_Title" at 11393.5,144.17 h70
  text "DESIGNED FOR:" at 11343.5,-23.5 h45
  text ".PRJ_Customer" at 11393.5,-163.5 h70
  text "D" at -416.5,-231.5 h70
  text "D" at 14383.5,-231.5 h70
  text "FILE NAME:" at 11343.5,-323.5 h45
  text ".PCB_File_Name_No_Path" at 11393.5,-443.5 h70
  text "Texas Instruments (TI) and/or its licensors do not warrant the accuracy or completeness of this specification" at 6374,-605.34 h45
  text "ENGINEER:" at 11343.5,-613.5 h45
  text "LAYOUT BY:" at 12848.5,-613.5 h45
  text "or any information contained therein. TI and/or its licensors do not warrant that this design will meet" at 6329.01,-718 h45
  text ".PRJ_Engineer" at 11393.5,-768.49 h70
  text ".PCB_Layout" at 12899,-768.49 h70
  text "the specifications, will be suitable for your application or fit for any particular purpose, or will operate in" at 6329.01,-830.67 h45
  text ".Layer_Name" at 577,-858.49 h60
  text "ALTIUM DESIGNER VERSION:" at 12848.5,-923.5 h45
  text "an implementation. TI and/or its licensors do not warrant that the design is production worthy. You should" at 6329.01,-943.33 h45
  text "completely validate and test your design implementation to confirm the system functionality for your application." at 6374,-1056 h45
  text ".print_Scale" at 11393.5,-1056.83 h70
  text ".Application_BuildNumber" at 12899,-1056.83 h70
  text "1" at 739.84,-1263.5 h70
  text "2" at 3235.5,-1263.5 h70
  text "3" at 5724.84,-1263.5 h70
  text "4" at 8231.51,-1263.5 h70
  text "5" at 10730.5,-1263.5 h70
  text "6" at 13235.5,-1263.5 h70
M10 Fab Notes:
  drawing of 212 lines, arcs and shapes, not listed
  text "DESIGN INFORMATION" at 12381.02,6810 h60
  text "(REFER ALSO ARRAY/PANEL PROFILING INFORMATION)" at 12019.46,6648.29 h60
  text "BOARD SIZE" at 11333.46,6644 h60
  text "3450MIL" at 11795.78,6516.18 h60
  text "X" at 12301.46,6516.18 h60
  text "4950MIL" at 12532.78,6516.18 h60
  text "Number of Layers :" at 11736.46,6319 h60
  text "2" at 12831.27,6309 h60
  text "MIN. TRACK WIDTH:" at 11736.46,6180 h60
  text "8" at 12832.7,6180 h60
  text "MIL" at 12987.46,6180 h60
  text "MIN. CLEARANCE:" at 11736.46,6048 h60
  text "8" at 12832.7,6048 h60
  text "MIL" at 12987.46,6048 h60
  text "MIN. VIA PAD SIZE:" at 11736.46,5916 h60
  text "24" at 12802.71,5916 h60
  text "MIL" at 12987.46,5916 h60
  text "0.05mm (2MIL)" at 12431.46,5774.29 h60
  text "MINIMUM ANNULAR RING" at 11407.23,5770 h60
  text "EXTERNAL" at 13139.46,5770 h60
  text "PER" at 11607.23,5652 h60
  text "IPC-D-275 CLASS 2 LEVEL C" at 11827.23,5652 h60
  text "MIL, HOLES" at 13315.46,5539.71 h60
  text "+/-" at 12923,5539 h60
  text "+/-" at 13777,5539 h60
  text "REGISTRATION TOLERANCES:" at 11407.23,5534 h60
  text "METAL" at 12607,5534 h60
  text "5" at 13183.2,5534 h60
  text "3" at 14016.2,5534 h60
  text "MIL" at 14132.46,5534 h60
  text "MATERIAL:" at 11332.46,5324.54 h60
  text "FR-4 High Tg" at 12318.9,5184.21 h60
  text "FR-408" at 11753.46,5175.64 h60
  text "X" at 12165.46,5175.64 h60
  text "OTHER" at 13241.46,5175.64 h60
  text "62 MIL (1.6mm) +/-10%" at 12073.56,5012.92 h60
  text "THICKNESS:" at 11407.23,5008.64 h60
  text "X" at 11945.4,5008.64 h60
  text "OTHER" at 13358.46,5008.64 h60
  text "TOLERANCE:" at 11407.23,4850.64 h60
  text "X" at 12246.53,4850.64 h60
  text "ANSI IPC-6012 TYPE 3 CLASS 2" at 12433.48,4850.64 h60
  text "OTHER +/-" at 12433.46,4694.64 h60
  text "BOW & TWIST:" at 11407.23,4537.64 h60
  text "X" at 12246.53,4537.64 h60
  text "ANSI IPC-6012 TYPE 3 CLASS 2" at 12433.48,4537.64 h60
  text "OTHER +/-" at 12433.46,4379.13 h60
  text "COPPER THICKNESS (FINISHED):" at 11332.46,4243.64 h60
  text "1.4MIL (1oz)" at 12212.46,4090.92 h60
  text "2MIL (1.4oz)" at 12979.46,4090.92 h60
  text "2.8MIL (2oz)" at 13706.46,4090.92 h60
  text "OUTER:" at 11689.46,4086.64 h60
  text "X" at 12084,4086 h60
  text "1.4MIL (1oz)" at 12212.46,3933.92 h60
  text "2.8MIL (2oz)" at 12979.46,3933.92 h60
  text "N/A" at 13706,3934.29 h60
  text "INNER SIGNAL:" at 11400.38,3929.64 h60
  text "X" at 12085.42,3929.64 h60
  text "DRILLING:" at 12234.46,3474.64 h60
  text "REFERENCE:" at 12309.23,3357.64 h60
  text "X" at 12957.46,3357.64 h60
  text "AS SHOWN" at 13144.46,3357.64 h60
  text "X" at 13858.46,3357.64 h60
  text "NC_DRILL FILES" at 13995.46,3357.64 h60
  text "PTH MIN COPPER THICKNESS:" at 12309.23,3199.64 h60
  text "X" at 13659.46,3199.64 h60
  text "1MIL" at 13796.46,3199.64 h60
  text "OTHER" at 14293.46,3199.64 h60
  text "BOARD FINISH:" at 12234.46,3040.64 h60
  text "SILKSCREEN:" at 12389.68,2922.64 h60
  text "X" at 13338.46,2922.64 h60
  text "TOP" at 13464.46,2922.64 h60
  text "X" at 13848.46,2922.64 h60
  text "BOTTOM" at 13975.46,2922.64 h60
  text "SILKSCREEN COLOR:" at 12389.68,2755.64 h60
  text "X" at 13337.42,2755.64 h60
  text "WHITE" at 13464.46,2755.64 h60
  text "OTHER" at 13975.46,2755.64 h60
  text "SOLDER RESIST COLOR:" at 12389.68,2585.64 h60
  text "X" at 12957.42,2426.44 h60
  text "GREEN" at 13084.46,2426.44 h60
  text "BLUE" at 13675.46,2426.44 h60
  text "OTHER" at 14213.46,2426.44 h60
  text "IMMERSION GOLD (ENIG)" at 13295.46,2237.92 h60
  text "ENEPIG" at 14633,2234.64 h60
  text "SURFACE FINISH:" at 12234.46,2233.64 h60
  text "X" at 13108.51,2233.64 h60
  text "IMM. TIN/SILVER OR EQUIV" at 12564,2076.64 h60
  text "OTHER" at 13995.46,2076.64 h60
  text "N.C. ROUTE" at 12393.46,2057.64 h60
  text "X" at 13072.46,2057.64 h60
  text "V. SCORE" at 13259.46,2057.64 h60
  text "CERTIFICATION:" at 11332.46,1920.64 h60
  text "MATERIALS AND WORKMANSHIP FOR ALL PCBS" at 12057.46,1920.64 h60
  text "ARRAY/PANEL:" at 12234.46,1897.64 h60
  text "CUT AND TRIM PER MECH LAYER 1" at 13295.46,1893.35 h60
  text "TO MEET OR EXCEED THE REQUIREMENTS OF:" at 12057.46,1822.64 h60
  text "X" at 11683.96,1686.13 h60
  text "ANSI IPC-A-600F CLASS ->" at 11822.96,1686.13 h60
  text "X" at 13462.02,1686.13 h60
  text "2" at 13580.96,1686.14 h60
  text "1" at 13265.96,1684.64 h60
  text "3" at 13934.96,1684.64 h60
  text "X" at 11686.02,1526.64 h60
  text "UL 94V-0" at 11822.96,1526.64 h60
  text "X" at 12498.02,1526.64 h60
  text "RoHS" at 12634.96,1526.64 h60
  text "OTHER" at 13279.36,1526.64 h60
  text "PER ORDER" at 13676.42,1526.64 h60
  text "ADDITIONAL REQUIREMENTS:" at 11332.46,1385.64 h60
  text "MICROSECTION:" at 11407.23,1270.64 h60
  text "YES" at 12312.96,1270.64 h60
  text "REQUIRED" at 13174.46,1114.49 h60
  text "BARE BOARD ELEC. TEST:" at 11407.23,1111.64 h60
  text "NONE" at 12712.96,1111.64 h60
  text "X" at 13047.46,1111.64 h60
  text "PER ORDER" at 13766.46,1111.64 h60
  text "MANUFACTURER'S UL:" at 11407.23,954.64 h60
  text "RAIL" at 12572.96,950.35 h60
  text "METAL" at 13064.77,950.35 h60
  text "X" at 13440,950 h60
  text "SILK" at 13576.46,950.35 h60
  text ".Layer_Name" at 577,-858.49 h60
M11 Gerber Information:
  lines w10: -292,-930.17 6308,-930.17 ; -292,-726.83 6310,-726.83 ; -292,-523.5 -292,-1133.5 3713,-1133.5 6310,-1133.5 6310,-523.5 -291.5,-523.5 -291.5,-1133.5 1284,-1133.5 ; 2173,-1133.5 2173,-523.5 ; 3440,-726.83 3440,-523.5 ; 4280,-726.83 4280,-523.5 ; 4902,-1140 4902,-937.17
  text "ALL ARTWORK VIEWED FROM TOP SIDE" at -228.5,-655.67 h60
  text "BOARD #:" at 2248,-655.67 h60
  text ".PRJ_Number" at 2793.5,-655.67 h60
  text "REV:" at 3638,-655.67 h60
  text ".PCB_Rev" at 3929.5,-655.67 h60
  text "SVN REV:" at 4476,-655.67 h60
  text ".VersionControl_RevNumber" at 4982,-655.67 h60
  text "LAYER NAME =" at -228.5,-858.49 h60
  text "PLOT NAME =" at -228.5,-1064.34 h60
  text ".plot_File_Name" at 577,-1064.34 h60
  text "GENERATED    :" at 2250,-1064.34 h60
  text ".Print_Date" at 3119.5,-1064.34 h60
  text ".Print_Time" at 3848.5,-1064.34 h60
  text "TEXAS INSTRUMENTS" at 5113,-1064.34 h60
M12 Stackup:
  lines w6: 11360,7690.5 14220,7690.5 ; 11360,7803.1 14220,7803.1 ; 11300,6966 ccw(c11336,6966) 11336,6930 14244,6930 ccw(c14244,6966) 14280,6966 14280,7904 ccw(c14244,7904) 14244,7940 11336,7940 ccw(c11336,7904) 11300,7904 11300,6966
  text "Layer Stack Up Detail for: PMP10260 REVA.PcbDoc" at 11360,7832.95 h52
  text "Layer" at 11360,7761.1 h26
  text "Gerber" at 12361.14,7761.1 h26
  text "Copper" at 13016.52,7761.1 h26
  text "Dielectric" at 13714.35,7761.1 h26
  text "Name" at 11360,7709.1 h26
  text "Document" at 12361.14,7709.1 h26
  text "Thickness" at 13016.52,7709.1 h26
  text "Material" at 13714.35,7709.1 h26
  text "Top Solder Mask" at 11360,7634.9 h36
  text "(.GTS)" at 12361.14,7634.9 h36
  text "Solder Resist" at 13714.35,7634.9 h36
  text "Top Layer" at 11360,7529.69 h36
  text "(.GTL)" at 12361.14,7529.69 h36
  text "2.8mil" at 13016.52,7529.69 h36
  text "FR-4" at 13714.35,7477.08 h36
  text "MidLayer1" at 11360,7424.48 h36
  text "(.G1)" at 12361.14,7424.48 h36
  text "2.8mil" at 13016.52,7424.48 h36
  text "FR-4" at 13714.35,7371.88 h36
  text "MidLayer2" at 11360,7319.27 h36
  text "(.G2)" at 12361.14,7319.27 h36
  text "2.8mil" at 13016.52,7319.27 h36
  text "FR-4" at 13714.35,7266.67 h36
  text "Bottom Layer" at 11360,7214.06 h36
  text "(.GBL)" at 12361.14,7214.06 h36
  text "2.8mil" at 13016.52,7214.06 h36
  text "Bottom Solder Mask" at 11360,7108.85 h36
  text "(.GBS)" at 12361.14,7108.85 h36
  text "Solder Resist" at 13714.35,7108.85 h36
  text ".Layer_Name" at 577,-858.49 h60
M13 Component Bodies Top:
  text ".Layer_Name" at 577,-858.49 h60
M14 Component Bodies Bottom:
  text ".Layer_Name" at 577,-858.49 h60
M15 Courtyards Top:
  text ".Layer_Name" at 577,-858.49 h60
M16 Courtyards Bottom:
  text ".Layer_Name" at 577,-858.49 h60
Drill Drawing:
  text "Drill Table" at 5930,60 h60
  text ".Layer_Name" at 577,-858.49 h60

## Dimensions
0,0 to 0,4724.41 on M2 Board Dimensions
0,0 to 5118.11,0 on M2 Board Dimensions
